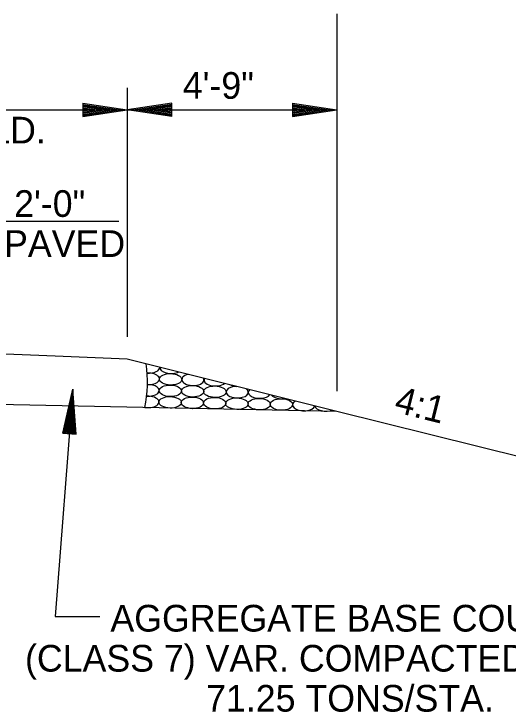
# Model space of a CAD drawing. Extents: x 2263886 to 2266026, y -3122850 to -3121850.
# Drawn here: x 2265621.05 to 2265632.15, y -3122417.04 to -3122401.35 of the extents above; entities that cross this region are included whole.
import ezdxf

# ---------------------------------------------------------------- set-up
doc = ezdxf.new("R2010")
doc.units = 0
doc.layers.add('R_Border Prem', color=7, linetype='Continuous')

msp = doc.modelspace()

# ---------------------------------------------------------------- linework, layer by layer
at = {"layer": 'R_Border Prem'}
for p, q in [((2265628.309, -3122401.346), (2265628.309, -3122409.826)), ((2265623.599, -3122403.003), (2265623.599, -3122408.603)), ((2265622.599, -3122403.353), (2265623.599, -3122403.503)), ((2265622.599, -3122403.353), (2265622.599, -3122403.653)), ((2265622.599, -3122403.378), (2265623.432, -3122403.503)), ((2265624.599, -3122403.353), (2265623.599, -3122403.503)), ((2265624.599, -3122403.378), (2265623.766, -3122403.503)), ((2265624.599, -3122403.653), (2265624.599, -3122403.353)), ((2265627.309, -3122403.353), (2265628.309, -3122403.503)), ((2265627.309, -3122403.353), (2265627.309, -3122403.653)), ((2265627.309, -3122403.378), (2265628.142, -3122403.503)), ((2265617.599, -3122403.503), (2265623.599, -3122403.503)), ((2265622.599, -3122403.404), (2265623.26, -3122403.503)), ((2265622.599, -3122403.429), (2265623.094, -3122403.503)), ((2265622.599, -3122403.455), (2265622.924, -3122403.503)), ((2265622.599, -3122403.48), (2265622.757, -3122403.503)), ((2265622.599, -3122403.653), (2265623.599, -3122403.503)), ((2265622.599, -3122403.552), (2265622.924, -3122403.503)), ((2265622.599, -3122403.603), (2265623.26, -3122403.503)), ((2265622.599, -3122403.628), (2265623.432, -3122403.503)), ((2265622.599, -3122403.578), (2265623.094, -3122403.503)), ((2265622.599, -3122403.527), (2265622.757, -3122403.503)), ((2265623.599, -3122403.503), (2265628.309, -3122403.503)), ((2265624.599, -3122403.653), (2265623.599, -3122403.503)), ((2265624.599, -3122403.628), (2265623.766, -3122403.503)), ((2265624.599, -3122403.404), (2265623.938, -3122403.503)), ((2265624.599, -3122403.603), (2265623.938, -3122403.503)), ((2265624.599, -3122403.429), (2265624.105, -3122403.503)), ((2265624.599, -3122403.578), (2265624.105, -3122403.503)), ((2265624.599, -3122403.454), (2265624.274, -3122403.503)), ((2265624.599, -3122403.552), (2265624.274, -3122403.503)), ((2265624.599, -3122403.48), (2265624.441, -3122403.503)), ((2265624.599, -3122403.527), (2265624.441, -3122403.503)), ((2265627.309, -3122403.404), (2265627.97, -3122403.503)), ((2265627.309, -3122403.429), (2265627.804, -3122403.503)), ((2265627.309, -3122403.455), (2265627.634, -3122403.503)), ((2265627.309, -3122403.48), (2265627.467, -3122403.503)), ((2265627.309, -3122403.653), (2265628.309, -3122403.503)), ((2265627.309, -3122403.552), (2265627.634, -3122403.503)), ((2265627.309, -3122403.603), (2265627.97, -3122403.503)), ((2265627.309, -3122403.628), (2265628.142, -3122403.503)), ((2265627.309, -3122403.578), (2265627.804, -3122403.503)), ((2265627.309, -3122403.527), (2265627.467, -3122403.503)), ((2265617.599, -3122406.003), (2265623.406, -3122406.003)), ((2265621.979, -3122409.038), (2265617.599, -3122408.863)), ((2265623.599, -3122409.103), (2265621.979, -3122409.038)), ((2265628.309, -3122410.281), (2265623.599, -3122409.103)), ((2265622.378, -3122409.78), (2265621.981, -3122414.893)), ((2265622.151, -3122410.766), (2265622.378, -3122409.78)), ((2265622.45, -3122410.789), (2265622.378, -3122409.78)), ((2265628.309, -3122410.281), (2265610.596, -3122409.926)), ((2265622.176, -3122410.768), (2265622.365, -3122409.947)), ((2265622.425, -3122410.787), (2265622.365, -3122409.947)), ((2265622.201, -3122410.769), (2265622.352, -3122410.118)), ((2265622.4, -3122410.785), (2265622.352, -3122410.118)), ((2265622.226, -3122410.771), (2265622.339, -3122410.284)), ((2265622.375, -3122410.783), (2265622.339, -3122410.284)), ((2265635.599, -3122412.103), (2265628.309, -3122410.281)), ((2265622.252, -3122410.773), (2265622.326, -3122410.453)), ((2265622.349, -3122410.781), (2265622.326, -3122410.453)), ((2265622.277, -3122410.775), (2265622.313, -3122410.62)), ((2265622.324, -3122410.779), (2265622.313, -3122410.62)), ((2265622.151, -3122410.766), (2265622.45, -3122410.789)), ((2265621.981, -3122414.893), (2265622.981, -3122414.893))]:
    msp.add_line(p, q, dxfattribs=at)
msp.add_arc((2265621.05, -3122409.615), 3, 348.8766, 7.7893, dxfattribs=at)
for centre, start_param, end_param in [((2265624.077, -3122409.289), 4.588076, 6.354801), ((2265624.577, -3122409.299), 3.072179, 5.520402), ((2265624.071, -3122409.548), 0.374579, 1.694354), ((2265625.072, -3122409.568), 1.976129, 6.616453), ((2265624.071, -3122409.548), 4.63336, 6.657764), ((2265625.572, -3122409.578), 2.853055, 5.739526), ((2265624.066, -3122409.807), 4.588686, 6.937388), ((2265624.066, -3122409.807), 0.654202, 1.649788), ((2265626.067, -3122409.847), 1.619877, 6.393503), ((2265626.072, -3122409.588), 3.935462, 4.65712), ((2265626.067, -3122409.847), 0.110318, 0.689519), ((2265626.567, -3122409.857), 2.640039, 5.952543), ((2265624.061, -3122410.066), 4.453496, 7.236085), ((2265624.061, -3122410.066), 0.9529, 1.695069), ((2265627.067, -3122409.867), 3.533684, 5.058897), ((2265627.562, -3122410.136), 2.422983, 6.169599), ((2265624.056, -3122410.325), 1.566843, 1.57475), ((2265624.556, -3122410.335), 1.566846, 1.574747), ((2265625.056, -3122410.345), 1.566849, 1.574744), ((2265625.556, -3122410.355), 1.566851, 1.574741), ((2265626.056, -3122410.365), 1.566855, 1.574738), ((2265626.556, -3122410.375), 1.566857, 1.574736), ((2265627.056, -3122410.385), 1.56686, 1.574733), ((2265627.556, -3122410.395), 1.566862, 1.57473), ((2265628.062, -3122410.146), 3.261227, 5.331355), ((2265628.056, -3122410.405), 1.566865, 1.574727)]:
    msp.add_ellipse(centre, major_axis=(0.25, -0.005), ratio=0.517889, start_param=start_param, end_param=end_param, dxfattribs=at)
for centre in [(2265624.571, -3122409.558), (2265624.566, -3122409.817), (2265625.066, -3122409.827), (2265625.566, -3122409.837), (2265624.561, -3122410.076), (2265625.061, -3122410.086), (2265625.561, -3122410.096), (2265626.061, -3122410.106), (2265626.561, -3122410.116), (2265627.061, -3122410.126)]:
    msp.add_ellipse(centre, major_axis=(0.25, -0.005), ratio=0.517889, dxfattribs=at)

# ---------------------------------------------------------------- texts
for s, p in [('4\'-9"', (2265624.845, -3122403.253)), ('SHLD.', (2265619.405, -3122404.258)), ('2\'-0"', (2265621.057, -3122405.908)), ('PAVED', (2265620.83, -3122406.808)), ('AGGREGATE BASE COURSE', (2265623.219, -3122415.229)), ('(CLASS 7) VAR. COMPACTED DEPTH', (2265621.301, -3122416.129)), ('71.25 TONS/STA.', (2265625.369, -3122417.029))]:
    msp.add_text(s, height=0.6, dxfattribs=at).set_placement(p)
msp.add_text('4:1', height=0.6, rotation=345.9638, dxfattribs=at).set_placement((2265629.571, -3122410.287))

doc.saveas('drawing.dxf')
